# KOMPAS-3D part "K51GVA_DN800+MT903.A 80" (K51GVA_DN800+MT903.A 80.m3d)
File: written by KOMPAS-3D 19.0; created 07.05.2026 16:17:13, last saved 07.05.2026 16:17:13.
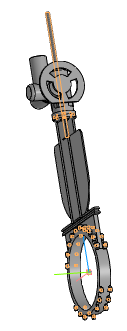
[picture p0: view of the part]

Document properties: Автор: Энергия; Полное имя файла: K51GVA_DN800+MT903.A 80.m3d

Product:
- Part/product: K51GVA_DN800+MT903.A 80
    Масса: 715.243
  - Component [detail]: Электропривод МТ903.А80 без блока управления  | Масса: 375.123; source file: ..\Электропривод МТ903.А\Электропривод МТ903.А80 F25 без блока управления.m3d
  - Component [detail]: K51GVA_DN800  | Масса: 340.12; source file: ..\K51GVA_DN50-DN1000_с фланцем\K51GVA_DN800.m3d

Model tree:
1. Элемент вращения:5  (with: Элемент выдавливания:10, Отверстие:1, Элемент выдавливания:23)

Referenced files in Z:\3.Личные\kachalov\3d для проектировщиков\x.x Тип_K21GVA_K51GVA. Задвижка\Электропривод МТ903.А\: Электропривод МТ903.А80 F25 без блока управления.m3d
Referenced files in Z:\3.Личные\kachalov\3d для проектировщиков\x.x Тип_K21GVA_K51GVA. Задвижка\K51GVA_DN50-DN1000_с фланцем\: K51GVA_DN800.m3d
